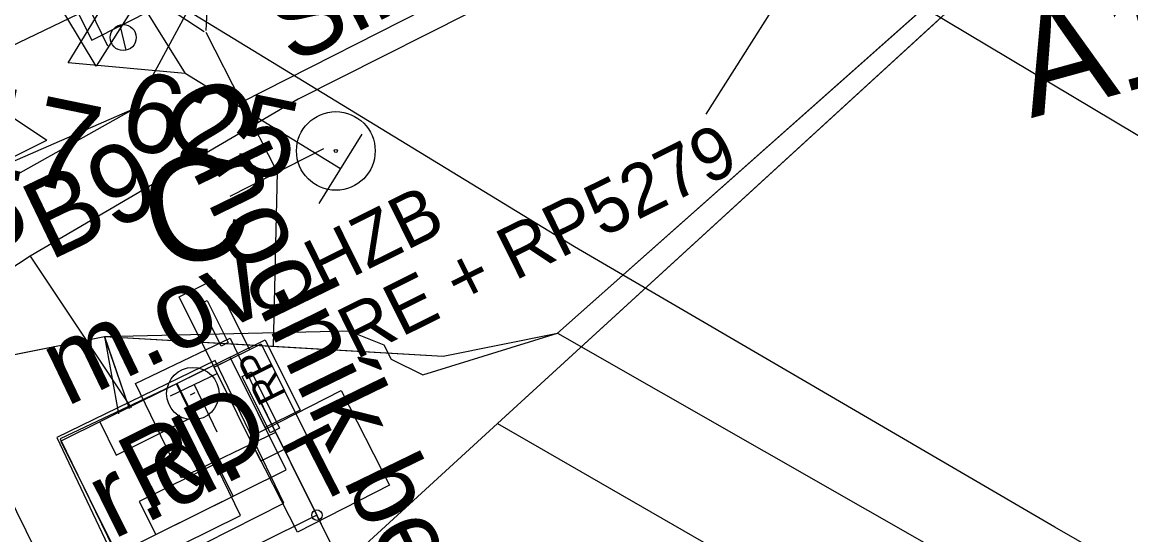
# Model space of a CAD drawing. Extents: x -9100 to -8660, y -10901 to -10569.
# Drawn here: x -8980.1 to -8958.96, y -10804.17 to -10794.39 of the extents above; entities that cross this region are included whole.
import ezdxf

# ---------------------------------------------------------------- set-up
doc = ezdxf.new("R2010")
doc.units = 0
for name, color, linetype in [('16_SSZT', 7, 'Continuous'), ('16_SSZT - DK', 7, 'Continuous'), ('17_ČD - telematika', 7, 'Continuous'), ('Default', 7, 'Continuous'), ('fotovoltaické panely', 7, 'Continuous'), ('HranDP', 7, 'Continuous'), ('Hranice parcel', 7, 'Continuous'), ('JC - SITU - Přejezd', 7, 'Continuous'), ('Parcelní čísla', 7, 'Continuous'), ('PS110241_Sdělovací zařízení', 7, 'Continuous'), ('SO118601 - rozvaděče', 7, 'Continuous'), ('SO118601 - rozvaděče  popis', 7, 'Continuous'), ('SO118601 - trasa NN', 7, 'Continuous'), ('SO118601 - uzemnění', 7, 'Continuous'), ('Vrstva 1', 7, 'Continuous'), ('Vrstva 16', 7, 'Continuous'), ('Vrstva 2', 7, 'Continuous'), ('Vrstva 27', 7, 'Continuous'), ('Vrstva 3', 7, 'Continuous'), ('Vrstva 33', 7, 'Continuous'), ('Vrstva 36', 7, 'Continuous'), ('Vrstva 4', 7, 'Continuous'), ('Vrstva 51', 7, 'Continuous'), ('Značky bodu BP', 7, 'Continuous')]:
    doc.layers.add(name, color=color, linetype=linetype)

# ---------------------------------------------------------------- blocks, each defined once
blk = doc.blocks.new('T')
at = {"layer": 'Default'}
blk.add_lwpolyline([(-9928, 10980), (9772, 10980), (9772, -9318), (-9928, -9318)], close=True, dxfattribs=at)
blk.add_text('T', height=12800, dxfattribs=at).set_placement((-5309, -6322))

msp = doc.modelspace()

# ---------------------------------------------------------------- linework, layer by layer
at = {"layer": '16_SSZT'}
msp.add_line((-8960.588, -10792.058), (-8969.887, -10800.323), dxfattribs=at)
for points in [[(-9074.585, -10817.612), (-9054.624, -10814.278), (-9033.944, -10809.249), (-9016.331, -10803.227), (-8993.207, -10794.934), (-8992.236, -10796.991), (-8989.816, -10802.65), (-8978.528, -10800.389), (-8972.071, -10800.763), (-8969.887, -10800.323), (-8960.588, -10792.058), (-8935.292, -10775.141), (-8919.684, -10767.375), (-8910.065, -10763.204), (-8903.876, -10759.887), (-8899.774, -10757.335), (-8892.343, -10752.193), (-8875.762, -10743.528)], [(-8898.973, -10756.95), (-8902.242, -10756.235), (-8903.938, -10756.596), (-8906.578, -10758.251), (-8908.097, -10761.436), (-8909.812, -10763.554), (-8921.931, -10769.83), (-8933.078, -10775.478), (-8951.398, -10784.881), (-8963.08, -10790.024), (-8966.715, -10791.759), (-8974.833, -10795.863), (-8979.944, -10798.857)], [(-8979.944, -10798.857), (-8981.563, -10799.921), (-8985.374, -10801.925), (-8986.378, -10802.086), (-8989.046, -10795.812), (-8990.238, -10793.404), (-8991.025, -10792.933)], [(-8979.944, -10798.857), (-8978.823, -10800.539), (-8978.016, -10801.749)]]:
    msp.add_lwpolyline(points, dxfattribs=at)
at = {"layer": '16_SSZT - DK'}
for points in [[(-8978.528, -10800.389), (-8972.071, -10800.763), (-8969.887, -10800.323), (-8960.588, -10792.058), (-8935.292, -10775.141), (-8919.684, -10767.375), (-8910.065, -10763.204), (-8903.876, -10759.887), (-8899.774, -10757.335), (-8892.343, -10752.193), (-8875.762, -10743.528)], [(-9074.585, -10817.612), (-9054.624, -10814.278), (-9033.944, -10809.249), (-9016.331, -10803.227), (-8993.207, -10794.934), (-8992.236, -10796.991), (-8989.816, -10802.65), (-8978.528, -10800.389)]]:
    msp.add_lwpolyline(points, dxfattribs=at)
at = {"layer": '17_ČD - telematika'}
for p, q in [((-8960.588, -10792.058), (-8969.887, -10800.323)), ((-8978.528, -10800.389), (-8978.261, -10801.866))]:
    msp.add_line(p, q, dxfattribs=at)
for points in [[(-8978.528, -10800.389), (-8972.071, -10800.763), (-8969.887, -10800.323), (-8960.588, -10792.058), (-8935.292, -10775.141), (-8919.684, -10767.375), (-8910.065, -10763.204), (-8903.876, -10759.887), (-8899.774, -10757.335), (-8892.343, -10752.193), (-8875.762, -10743.528)], [(-8973.866, -10800.284), (-8973.203, -10800.546), (-8973.06, -10800.825), (-8972.46, -10801.12), (-8969.887, -10800.323), (-8960.588, -10792.058), (-8935.292, -10775.141), (-8919.684, -10767.375), (-8910.065, -10763.204), (-8903.876, -10759.887), (-8899.774, -10757.335), (-8892.343, -10752.193), (-8879.745, -10745.609)], [(-9074.585, -10817.612), (-9054.624, -10814.278), (-9033.944, -10809.249), (-9016.331, -10803.227), (-8993.207, -10794.934), (-8992.236, -10796.991), (-8989.816, -10802.65), (-8978.528, -10800.389)], [(-9074.585, -10817.612), (-9054.624, -10814.278), (-9033.944, -10809.249), (-9016.331, -10803.227), (-8993.207, -10794.934), (-8992.236, -10796.991), (-8989.816, -10802.65), (-8978.528, -10800.389)], [(-8978.528, -10800.389), (-8973.866, -10800.284)]]:
    msp.add_lwpolyline(points, dxfattribs=at)
at = {"layer": 'fotovoltaické panely'}
for points in [[(-8978.305, -10802.651), (-8976.828, -10801.917), (-8977.141, -10801.286), (-8978.618, -10802.02)], [(-8977.551, -10804.17), (-8976.073, -10803.436), (-8976.386, -10802.805), (-8977.864, -10803.539)]]:
    msp.add_lwpolyline(points, close=True, dxfattribs=at)
at = {"layer": 'HranDP'}
for p, q in [((-8960.171, -10792.093), (-8971.031, -10802.048)), ((-8971.031, -10802.048), (-8953.298, -10812.273))]:
    msp.add_line(p, q, dxfattribs=at)
at = {"layer": 'Hranice parcel'}
msp.add_line((-8971.031, -10802.048), (-8953.298, -10812.273), dxfattribs=at)
for points in [[(-8958.322, -10790.401), (-8960.171, -10792.093), (-8971.031, -10802.048)], [(-9068.32, -10829.079), (-9052.248, -10826.546), (-9032.208, -10821.544), (-9013.309, -10815.388), (-8989.56, -10805.911), (-8975.914, -10806.525), (-8971.031, -10802.048)]]:
    msp.add_lwpolyline(points, dxfattribs=at)
at = {"layer": 'JC - SITU - Přejezd'}
msp.add_line((-8978.463, -10794.848), (-8979.121, -10793.5), dxfattribs=at)
at = {"layer": 'PS110241_Sdělovací zařízení'}
for points in [[(-8978.049, -10801.771), (-8978.528, -10800.389), (-8972.071, -10800.763), (-8969.887, -10800.323), (-8960.588, -10792.058), (-8962.993, -10790.328), (-8963.989, -10790.84), (-8967.772, -10783.915), (-8971.948, -10785.974), (-8985.392, -10779.074)], [(-8974.984, -10800.594), (-8972.071, -10800.763), (-8969.887, -10800.323), (-8956.098, -10808.21)]]:
    msp.add_lwpolyline(points, dxfattribs=at)
at = {"layer": 'SO118601 - rozvaděče'}
for points in [[(-8976.433, -10799.299), (-8975.765, -10800.642), (-8976.437, -10800.976), (-8977.104, -10799.632)], [(-8976.568, -10799.701), (-8976.168, -10800.507), (-8976.302, -10800.573), (-8976.702, -10799.767)], [(-8975.548, -10802.767), (-8976.437, -10800.976), (-8975.542, -10800.531), (-8974.652, -10802.322)], [(-8975.367, -10802.231), (-8975.901, -10801.156), (-8975.722, -10801.067), (-8975.188, -10802.142)]]:
    msp.add_lwpolyline(points, close=True, dxfattribs=at)
at = {"layer": 'SO118601 - trasa NN'}
msp.add_lwpolyline([(-8973.165, -10825.461), (-8972.695, -10823.704), (-8975.687, -10806.074), (-8973.81, -10805.142), (-8975.545, -10801.649)], dxfattribs=at)
at = {"layer": 'SO118601 - uzemnění'}
for points in [[(-8975.545, -10801.649), (-8974.477, -10803.798), (-8979.045, -10806.067), (-8979.49, -10805.171), (-8980.557, -10803.022)], [(-8980.557, -10803.022), (-8981.898, -10803.694), (-8979.721, -10808.077), (-8973.81, -10805.142), (-8973.81, -10805.142), (-8974.477, -10803.798)]]:
    msp.add_lwpolyline(points, dxfattribs=at)
msp.add_circle((-8974.477, -10803.798), 0.1, dxfattribs=at)
at = {"layer": 'Vrstva 1'}
for p, q in [((-8960.588, -10792.058), (-8969.887, -10800.323)), ((-8975.238, -10797.256), (-8975.314, -10800.575)), ((-8989.816, -10802.65), (-8978.528, -10800.389)), ((-8978.528, -10800.389), (-8978.061, -10801.743)), ((-8978.528, -10800.389), (-8975.314, -10800.575)), ((-8975.797, -10800.619), (-8978.061, -10801.743))]:
    msp.add_line(p, q, dxfattribs=at)
for points in [[(-9071.078, -10824.031), (-9068.55, -10823.67), (-9059.39, -10822.051), (-9049.732, -10820.012), (-9040.576, -10817.765), (-9031.032, -10815.085), (-9021.565, -10812.071), (-9019.212, -10811.266), (-9010.687, -10808.158), (-9001.881, -10804.632), (-8992.751, -10800.668), (-8983.884, -10796.567), (-8979.025, -10794.235), (-8968.639, -10789.006), (-8963.908, -10786.557), (-8955.013, -10781.841), (-8946.607, -10777.298), (-8938.34, -10772.786), (-8931.689, -10769.156), (-8930.764, -10768.65), (-8923.574, -10764.727), (-8915.206, -10760.16)], [(-8975.314, -10800.575), (-8974.984, -10800.594), (-8972.071, -10800.763), (-8969.887, -10800.323), (-8969.887, -10800.323)]]:
    msp.add_lwpolyline(points, dxfattribs=at)
at = {"layer": 'Vrstva 16'}
msp.add_lwpolyline([(-8979.437, -10802.319), (-8978.119, -10805.097), (-8975.105, -10803.567), (-8976.418, -10800.849), (-8979.437, -10802.319)], dxfattribs=at)
at = {"layer": 'Vrstva 2'}
for p, q in [((-8976.588, -10794.551), (-8976.401, -10790.556)), ((-8979.967, -10792.369), (-8976.626, -10794.57)), ((-8975.918, -10795.919), (-8970.569, -10793.2)), ((-8982.945, -10794.411), (-8979.628, -10796.646)), ((-8976.598, -10794.582), (-8975.238, -10797.256)), ((-8983.211, -10798.424), (-8979.628, -10796.646)), ((-8976.129, -10797.71), (-8974.347, -10796.803))]:
    msp.add_line(p, q, dxfattribs=at)
for points in [[(-8975.466, -10802.129), (-8976.133, -10800.786), (-8975.461, -10800.452), (-8974.794, -10801.796)], [(-8978.29, -10804.537), (-8975.066, -10802.935), (-8976.133, -10800.786), (-8979.357, -10802.387)]]:
    msp.add_lwpolyline(points, close=True, dxfattribs=at)
at = {"layer": 'Vrstva 27'}
msp.add_line((-8976.888, -10801.502), (-8976.798, -10801.459), dxfattribs=at)
msp.add_circle((-8976.843, -10801.48), 0.5, dxfattribs=at)
at = {"layer": 'Vrstva 33'}
for p, q in [((-8977.266, -10801.521), (-8976.365, -10801.088)), ((-8976.816, -10801.304), (-8976.383, -10802.206))]:
    msp.add_line(p, q, dxfattribs=at)
msp.add_lwpolyline([(-8977.934, -10801.286), (-8976.131, -10800.421), (-8975.265, -10802.224), (-8977.068, -10803.089), (-8977.934, -10801.286)], dxfattribs=at)
at = {"layer": 'Vrstva 36'}
msp.add_lwpolyline([(-8979.373, -10802.34), (-8978.135, -10804.894), (-8975.937, -10803.804), (-8977.157, -10801.29), (-8979.373, -10802.34)], dxfattribs=at)
at = {"layer": 'Vrstva 4'}
for p, q in [((-8967.056, -10796.145), (-8964.384, -10791.919)), ((-8978.115, -10794.924), (-8978.226, -10794.448)), ((-8974.434, -10797.85), (-8973.617, -10796.526))]:
    msp.add_line(p, q, dxfattribs=at)
for points in [[(-8969.132, -10788.626), (-8979.273, -10793.733), (-8978.768, -10794.734), (-8968.631, -10789.599), (-8969.132, -10788.626)], [(-8977.943, -10796.031), (-8976.938, -10794.174), (-8968.343, -10789.807)], [(-8982.779, -10791.441), (-8979.841, -10793.302), (-8977.619, -10793.541), (-8978.683, -10795.232), (-8979.841, -10793.302)], [(-8974.026, -10797.188), (-8976.991, -10795.373), (-8979.217, -10795.166), (-8978.179, -10793.459), (-8976.991, -10795.373)], [(-9070.351, -10825.361), (-9061.299, -10824.136), (-9034.584, -10818.011), (-9006.652, -10808.416), (-8988.076, -10800.451), (-8977.943, -10796.031)], [(-9070.034, -10825.943), (-9061.152, -10824.662), (-9034.438, -10818.416), (-9006.327, -10808.806), (-8987.566, -10801.434), (-8977.943, -10796.031)]]:
    msp.add_lwpolyline(points, dxfattribs=at)
msp.add_circle((-8978.17, -10794.686), 0.248, dxfattribs=at)
at = {"layer": 'Vrstva 51'}
msp.add_lwpolyline([(-8948.497, -10810.867), (-8960.406, -10804.026), (-8969.567, -10798.679), (-8976.938, -10794.174), (-8968.343, -10789.807), (-8967.358, -10791.334), (-8964.078, -10793.407), (-8956.463, -10797.959), (-8944.942, -10804.675)], dxfattribs=at)
at = {"layer": 'Značky bodu BP'}
for radius in [0.75, 0.03]:
    msp.add_circle((-8974.116, -10796.849), radius, dxfattribs=at)

# ---------------------------------------------------------------- block references
at = {"layer": 'PS110241_Sdělovací zařízení', "xscale": 0.00010000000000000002, "yscale": 9.999999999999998e-05, "rotation": 27.14898456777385}
msp.add_blockref('T', (-8974.386, -10802.843), dxfattribs=at)

# ---------------------------------------------------------------- texts
at = {"layer": 'Parcelní čísla'}
msp.add_text('1217', height=1.7, rotation=348.3687, dxfattribs=at).set_placement((-8983.775, -10796.682))
at = {"layer": 'SO118601 - rozvaděče  popis'}
for s, p in [('RE + RP5279', (-8973.735, -10800.837)), ('HZB', (-8974.375, -10799.548))]:
    msp.add_text(s, height=1, rotation=26.4087, dxfattribs=at).set_placement(p)
at = {"layer": 'Vrstva 16'}
msp.add_text('Chodník beton', height=1.5, rotation=295.9653, dxfattribs=at).set_placement((-8977.503, -10795.912))
at = {"layer": 'Vrstva 2'}
for s, height, rotation, p in [('RP', 0.5625, 116.4091, (-8975.045, -10801.502)), ('RD', 1.44, 26.6162, (-8977.755, -10803.739))]:
    msp.add_text(s, height=height, rotation=rotation, dxfattribs=at).set_placement(p)
at = {"layer": 'Vrstva 27'}
for s, p in [('PB9', (-8980.785, -10799.534)), ('m.ov.', (-8979.26, -10801.738))]:
    msp.add_text(s, height=1.5, rotation=25.6404, dxfattribs=at).set_placement(p)
at = {"layer": 'Vrstva 3'}
for s, p in [('A1', (-8960.862, -10796.225)), ('C', (-8977.475, -10799.167))]:
    msp.add_text(s, height=2, rotation=15.4127, dxfattribs=at).set_placement(p)
at = {"layer": 'Vrstva 36'}
msp.add_text('r.d.', height=1.5, rotation=26.3829, dxfattribs=at).set_placement((-8978.368, -10804.275))
at = {"layer": 'Vrstva 51'}
msp.add_text('Silnice asf.', height=1.5, rotation=26.9338, dxfattribs=at).set_placement((-8974.951, -10795.216))
at = {"layer": 'Značky bodu BP'}
msp.add_text('625', height=1.5, rotation=348.3687, dxfattribs=at).set_placement((-8978.286, -10796.756))

doc.saveas('drawing.dxf')
